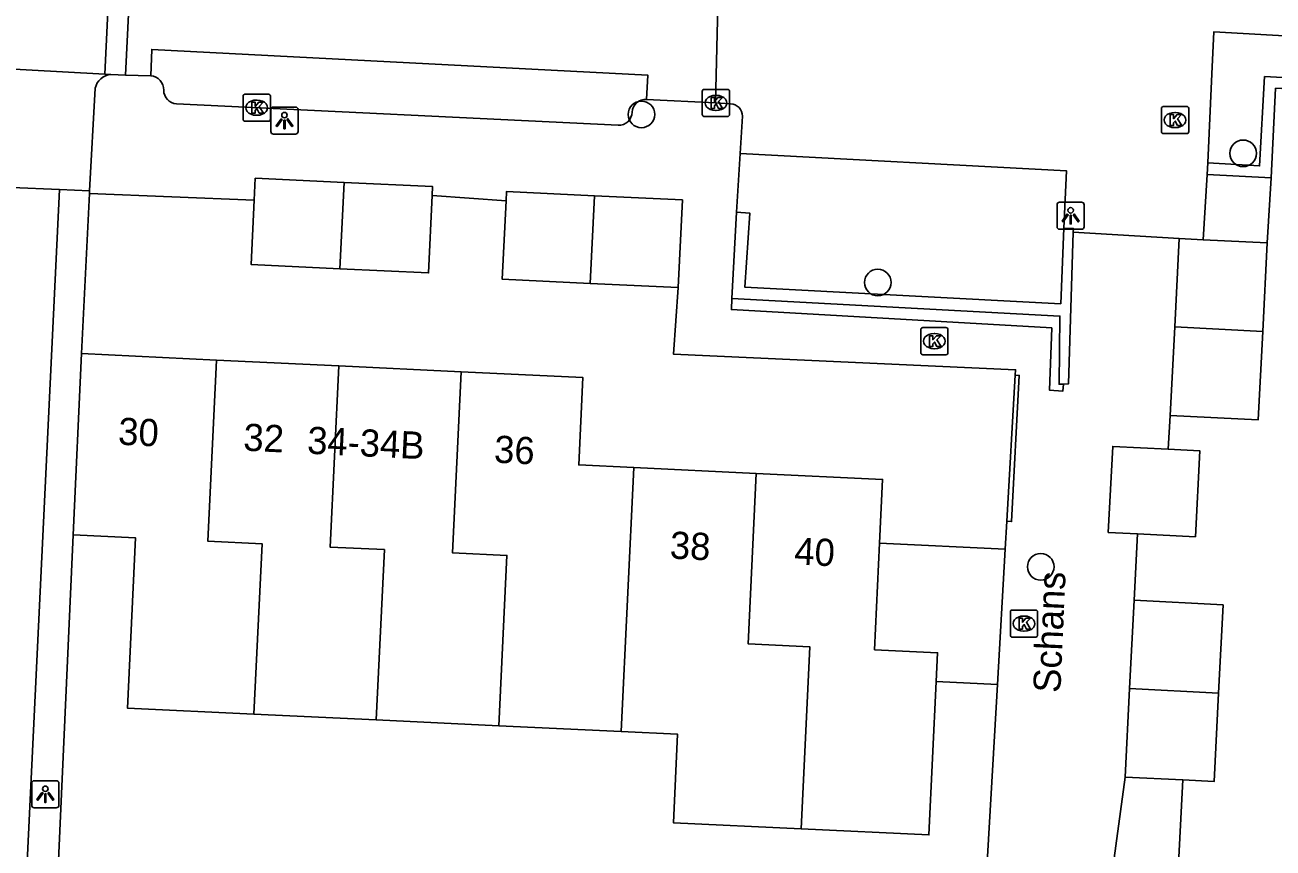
# Model space of a CAD drawing. Extents: x 162990 to 165007, y 383433 to 384336.
# Drawn here: x 164519.96 to 164565.87, y 383571.15 to 383601.43 of the extents above; entities that cross this region are included whole.
import ezdxf

# ---------------------------------------------------------------- set-up
doc = ezdxf.new("R2010")
doc.units = 0
for name, color, linetype in [('IMGEO_Boom', 7, 'Continuous'), ('IMGEO_Haag', 7, 'Continuous'), ('IMGEO_Kolk', 7, 'Continuous'), ('IMGEO_Lichtpunt', 7, 'Continuous'), ('IMGEO_Muur', 7, 'Continuous'), ('IMGEO_Openbare_ruimte_label', 7, 'Continuous'), ('IMGEO_Pand', 7, 'Continuous'), ('IMGEO_Pand_nummerreeks', 7, 'Continuous'), ('IMGEO_Parkeervlak_open', 7, 'Continuous'), ('IMGEO_Rijbaan_lokaal_open', 7, 'Continuous'), ('IMGEO_Voetpad_open', 7, 'Continuous')]:
    doc.layers.add(name, color=color, linetype=linetype)

msp = doc.modelspace()

# ---------------------------------------------------------------- linework, layer by layer
at = {"layer": 'IMGEO_Boom'}
for centre in [(164542.637, 383598.142), (164564.769, 383596.71), (164551.33, 383591.959), (164557.324, 383581.501)]:
    msp.add_circle(centre, 0.489, dxfattribs=at)
at = {"layer": 'IMGEO_Haag'}
msp.add_lwpolyline([(164556.385, 383588.543), (164556.077, 383583.176)], dxfattribs=at)
at = {"layer": 'IMGEO_Kolk'}
for p, q in [((164544.951, 383599.063), (164545.803, 383599.063)), ((164527.988, 383597.963), (164527.988, 383598.815)), ((164528.063, 383598.889), (164528.915, 383598.889)), ((164528.476, 383598.669), (164528.501, 383598.669)), ((164528.989, 383598.815), (164528.989, 383597.963)), ((164544.876, 383598.137), (164544.876, 383598.989)), ((164545.364, 383598.843), (164545.389, 383598.843)), ((164545.877, 383598.989), (164545.877, 383598.137)), ((164528.499, 383598.109), (164528.474, 383598.109)), ((164545.387, 383598.283), (164545.362, 383598.283)), ((164561.765, 383597.509), (164561.765, 383598.361)), ((164561.84, 383598.435), (164562.692, 383598.435)), ((164562.253, 383598.215), (164562.278, 383598.215)), ((164562.766, 383598.361), (164562.766, 383597.509)), ((164528.915, 383597.889), (164528.063, 383597.889)), ((164545.803, 383598.063), (164544.951, 383598.063)), ((164562.276, 383597.655), (164562.251, 383597.655)), ((164562.692, 383597.435), (164561.84, 383597.435)), ((164552.986, 383590.302), (164553.838, 383590.302)), ((164552.911, 383589.376), (164552.911, 383590.228)), ((164553.399, 383590.082), (164553.424, 383590.082)), ((164553.912, 383590.228), (164553.912, 383589.376)), ((164553.422, 383589.522), (164553.397, 383589.522)), ((164553.838, 383589.302), (164552.986, 383589.302)), ((164556.207, 383578.983), (164556.207, 383579.835)), ((164556.282, 383579.909), (164557.134, 383579.909)), ((164557.208, 383579.835), (164557.208, 383578.983)), ((164556.695, 383579.689), (164556.72, 383579.689)), ((164557.134, 383578.909), (164556.282, 383578.909)), ((164556.718, 383579.129), (164556.693, 383579.129))]:
    msp.add_line(p, q, dxfattribs=at)
for points in [[(164544.951, 383599.063), (164545.803, 383599.063)], [(164527.988, 383597.963), (164527.988, 383598.815)], [(164528.063, 383598.889), (164528.915, 383598.889)], [(164528.309, 383598.589), (164528.432, 383598.589), (164528.432, 383598.438), (164528.562, 383598.589), (164528.726, 383598.589), (164528.58, 383598.438), (164528.733, 383598.189), (164528.581, 383598.189), (164528.496, 383598.353), (164528.432, 383598.286), (164528.432, 383598.189), (164528.309, 383598.189), (164528.309, 383598.589)], [(164528.989, 383598.815), (164528.989, 383597.963)], [(164544.876, 383598.137), (164544.876, 383598.989)], [(164545.197, 383598.763), (164545.32, 383598.763), (164545.32, 383598.612), (164545.45, 383598.763), (164545.614, 383598.763), (164545.468, 383598.612), (164545.621, 383598.363), (164545.469, 383598.363), (164545.384, 383598.527), (164545.32, 383598.46), (164545.32, 383598.363), (164545.197, 383598.363), (164545.197, 383598.763)], [(164545.877, 383598.989), (164545.877, 383598.137)], [(164561.765, 383597.509), (164561.765, 383598.361)], [(164561.84, 383598.435), (164562.692, 383598.435)], [(164562.086, 383598.135), (164562.209, 383598.135), (164562.209, 383597.984), (164562.339, 383598.135), (164562.503, 383598.135), (164562.357, 383597.984), (164562.51, 383597.735), (164562.358, 383597.735), (164562.273, 383597.899), (164562.209, 383597.832), (164562.209, 383597.735), (164562.086, 383597.735), (164562.086, 383598.135)], [(164562.766, 383598.361), (164562.766, 383597.509)], [(164528.915, 383597.889), (164528.063, 383597.889)], [(164545.803, 383598.063), (164544.951, 383598.063)], [(164562.692, 383597.435), (164561.84, 383597.435)], [(164552.986, 383590.302), (164553.838, 383590.302)], [(164552.911, 383589.376), (164552.911, 383590.228)], [(164553.232, 383590.002), (164553.355, 383590.002), (164553.355, 383589.851), (164553.485, 383590.002), (164553.649, 383590.002), (164553.503, 383589.851), (164553.656, 383589.602), (164553.504, 383589.602), (164553.419, 383589.766), (164553.355, 383589.699), (164553.355, 383589.602), (164553.232, 383589.602), (164553.232, 383590.002)], [(164553.912, 383590.228), (164553.912, 383589.376)], [(164553.838, 383589.302), (164552.986, 383589.302)], [(164556.207, 383578.983), (164556.207, 383579.835)], [(164556.282, 383579.909), (164557.134, 383579.909)], [(164557.208, 383579.835), (164557.208, 383578.983)], [(164556.528, 383579.609), (164556.651, 383579.609), (164556.651, 383579.458), (164556.781, 383579.609), (164556.945, 383579.609), (164556.799, 383579.458), (164556.952, 383579.209), (164556.8, 383579.209), (164556.715, 383579.373), (164556.651, 383579.306), (164556.651, 383579.209), (164556.528, 383579.209), (164556.528, 383579.609)], [(164557.134, 383578.909), (164556.282, 383578.909)]]:
    msp.add_lwpolyline(points, dxfattribs=at)
for centre, start, end in [((164544.953, 383598.987), 91.552, 178.448), ((164544.953, 383598.987), 91.552, 178.448), ((164545.801, 383598.987), 1.552, 88.448), ((164545.801, 383598.987), 1.552, 88.448), ((164528.065, 383598.813), 91.552, 178.448), ((164528.065, 383598.813), 91.552, 178.448), ((164528.913, 383598.813), 1.552, 88.448), ((164528.913, 383598.813), 1.552, 88.448), ((164544.953, 383598.139), 181.552, 268.448), ((164544.953, 383598.139), 181.552, 268.448), ((164545.801, 383598.139), 271.552, 358.448), ((164545.801, 383598.139), 271.552, 358.448), ((164561.842, 383598.359), 91.552, 178.448), ((164561.842, 383598.359), 91.552, 178.448), ((164562.69, 383598.359), 1.552, 88.448), ((164562.69, 383598.359), 1.552, 88.448), ((164528.065, 383597.965), 181.552, 268.448), ((164528.065, 383597.965), 181.552, 268.448), ((164528.913, 383597.965), 271.552, 358.448), ((164528.913, 383597.965), 271.552, 358.448), ((164561.842, 383597.511), 181.552, 268.448), ((164561.842, 383597.511), 181.552, 268.448), ((164562.69, 383597.511), 271.552, 358.448), ((164562.69, 383597.511), 271.552, 358.448), ((164552.988, 383590.226), 91.552, 178.448), ((164552.988, 383590.226), 91.552, 178.448), ((164553.836, 383590.226), 1.552, 88.448), ((164553.836, 383590.226), 1.552, 88.448), ((164552.988, 383589.378), 181.552, 268.448), ((164552.988, 383589.378), 181.552, 268.448), ((164553.836, 383589.378), 271.552, 358.448), ((164553.836, 383589.378), 271.552, 358.448), ((164556.284, 383579.833), 91.552, 178.448), ((164556.284, 383579.833), 91.552, 178.448), ((164557.132, 383579.833), 1.552, 88.448), ((164557.132, 383579.833), 1.552, 88.448), ((164556.284, 383578.985), 181.552, 268.448), ((164556.284, 383578.985), 181.552, 268.448), ((164557.132, 383578.985), 271.552, 358.448), ((164557.132, 383578.985), 271.552, 358.448)]:
    msp.add_arc(centre, 0.0765, start, end, dxfattribs=at)
for centre, major_axis, ratio, start_param, end_param in [((164528.475, 383598.389), (-0.387, 0.002), 0.722429, 4.712389, 7.853982), ((164528.5, 383598.389), (-0.39, 0.002), 0.717154, 1.570796, 4.712389), ((164545.363, 383598.563), (-0.387, 0.002), 0.722429, 4.712389, 7.853982), ((164545.388, 383598.563), (-0.39, 0.002), 0.717154, 1.570796, 4.712389), ((164562.252, 383597.935), (-0.387, 0.002), 0.722429, 4.712389, 7.853982), ((164562.277, 383597.935), (-0.39, 0.002), 0.717154, 1.570796, 4.712389), ((164553.398, 383589.802), (-0.387, 0.002), 0.722429, 4.712389, 7.853982), ((164553.423, 383589.802), (-0.39, 0.002), 0.717154, 1.570796, 4.712389), ((164556.694, 383579.409), (-0.387, 0.002), 0.722429, 4.712389, 7.853982), ((164556.719, 383579.409), (-0.39, 0.002), 0.717154, 1.570796, 4.712389)]:
    msp.add_ellipse(centre, major_axis=major_axis, ratio=ratio, start_param=start_param, end_param=end_param, dxfattribs=at)
at = {"layer": 'IMGEO_Lichtpunt'}
for p, q in [((164529.01, 383598.318), (164529.01, 383597.511)), ((164529.01, 383598.318), (164529.01, 383597.511)), ((164529.912, 383598.413), (164529.104, 383598.413)), ((164529.912, 383598.413), (164529.104, 383598.413)), ((164530.006, 383597.511), (164530.006, 383598.318)), ((164530.006, 383597.511), (164530.006, 383598.318)), ((164529.104, 383597.417), (164529.912, 383597.417)), ((164529.104, 383597.417), (164529.912, 383597.417)), ((164558.828, 383594.911), (164558.02, 383594.911)), ((164558.828, 383594.911), (164558.02, 383594.911)), ((164557.926, 383594.816), (164557.926, 383594.009)), ((164557.926, 383594.816), (164557.926, 383594.009)), ((164558.922, 383594.009), (164558.922, 383594.816)), ((164558.922, 383594.009), (164558.922, 383594.816)), ((164558.02, 383593.915), (164558.828, 383593.915)), ((164558.02, 383593.915), (164558.828, 383593.915)), ((164520.214, 383573.536), (164520.214, 383572.729)), ((164520.214, 383573.536), (164520.214, 383572.729)), ((164521.116, 383573.631), (164520.308, 383573.631)), ((164521.116, 383573.631), (164520.308, 383573.631)), ((164521.21, 383572.729), (164521.21, 383573.536)), ((164521.21, 383572.729), (164521.21, 383573.536)), ((164520.308, 383572.635), (164521.116, 383572.635)), ((164520.308, 383572.635), (164521.116, 383572.635))]:
    msp.add_line(p, q, dxfattribs=at)
for points in [[(164529.384, 383597.982), (164529.423, 383597.954), (164529.235, 383597.692), (164529.197, 383597.719), (164529.384, 383597.982)], [(164529.486, 383597.934), (164529.533, 383597.934), (164529.533, 383597.612), (164529.486, 383597.612), (164529.486, 383597.934)], [(164529.596, 383597.954), (164529.634, 383597.981), (164529.821, 383597.719), (164529.782, 383597.691), (164529.596, 383597.954)], [(164558.3, 383594.48), (164558.339, 383594.452), (164558.151, 383594.19), (164558.113, 383594.217), (164558.3, 383594.48)], [(164558.402, 383594.432), (164558.449, 383594.432), (164558.449, 383594.11), (164558.402, 383594.11), (164558.402, 383594.432)], [(164558.512, 383594.452), (164558.55, 383594.479), (164558.737, 383594.217), (164558.698, 383594.189), (164558.512, 383594.452)], [(164520.588, 383573.2), (164520.627, 383573.172), (164520.439, 383572.91), (164520.401, 383572.937), (164520.588, 383573.2)], [(164520.69, 383573.152), (164520.737, 383573.152), (164520.737, 383572.83), (164520.69, 383572.83), (164520.69, 383573.152)], [(164520.8, 383573.172), (164520.838, 383573.199), (164521.025, 383572.937), (164520.986, 383572.909), (164520.8, 383573.172)]]:
    msp.add_lwpolyline(points, dxfattribs=at)
for centre in [(164529.509, 383598.116), (164558.425, 383594.614), (164520.713, 383573.334)]:
    msp.add_circle(centre, 0.0994, dxfattribs=at)
for centre, start, end in [((164529.104, 383598.318), 90, 180), ((164529.104, 383598.318), 90, 180), ((164529.912, 383598.318), 0, 90), ((164529.912, 383598.318), 0, 90), ((164529.104, 383597.511), 180, 270), ((164529.104, 383597.511), 180, 270), ((164529.912, 383597.511), 270, 0), ((164529.912, 383597.511), 270, 360), ((164558.02, 383594.816), 90, 180), ((164558.02, 383594.816), 90, 180), ((164558.828, 383594.816), 0, 90), ((164558.828, 383594.816), 0, 90), ((164558.02, 383594.009), 180, 270), ((164558.02, 383594.009), 180, 270), ((164558.828, 383594.009), 270, 0), ((164558.828, 383594.009), 270, 360), ((164520.308, 383573.536), 90, 180), ((164520.308, 383573.536), 90, 180), ((164521.116, 383573.536), 0, 90), ((164521.116, 383573.536), 0, 90), ((164520.308, 383572.729), 180, 270), ((164520.308, 383572.729), 180, 270), ((164521.116, 383572.729), 270, 0), ((164521.116, 383572.729), 270, 360)]:
    msp.add_arc(centre, 0.0946, start, end, dxfattribs=at)
at = {"layer": 'IMGEO_Muur'}
for points in [[(164563.466, 383596.357), (164565.372, 383596.247), (164565.556, 383599.531), (164570.369, 383599.262)], [(164570.349, 383598.879), (164565.965, 383599.104), (164565.796, 383595.808)], [(164563.44, 383595.929), (164563.466, 383596.357)], [(164565.796, 383595.808), (164563.44, 383595.929)], [(164545.958, 383591.369), (164546.139, 383594.544)], [(164558.178, 383593.954), (164558.06, 383591.174), (164546.443, 383591.785), (164546.621, 383594.514), (164546.139, 383594.544)], [(164558.521, 383593.815), (164558.346, 383588.235), (164558.156, 383588.224)], [(164558.178, 383593.954), (164558.525, 383593.945), (164558.521, 383593.815)], [(164558.156, 383588.224), (164557.996, 383588.215), (164558.03, 383590.725), (164545.958, 383591.369)], [(164521.732, 383582.678), (164521.067, 383567.706)]]:
    msp.add_lwpolyline(points, dxfattribs=at)
at = {"layer": 'IMGEO_Pand'}
for points in [[(164528.397, 383594.983), (164528.436, 383595.795), (164531.698, 383595.639)], [(164531.698, 383595.639), (164531.545, 383592.465)], [(164531.698, 383595.639), (164534.958, 383595.484), (164534.942, 383595.154)], [(164531.545, 383592.465), (164528.284, 383592.62), (164528.397, 383594.983)], [(164534.942, 383595.154), (164534.806, 383592.309), (164531.545, 383592.465)], [(164540.758, 383591.924), (164537.52, 383592.078), (164537.658, 383594.958)], [(164537.658, 383594.958), (164537.674, 383595.303), (164540.912, 383595.149)], [(164540.912, 383595.149), (164540.758, 383591.924)], [(164540.912, 383595.149), (164544.148, 383594.995), (164543.994, 383591.77)], [(164562.251, 383590.325), (164562.417, 383593.578)], [(164562.417, 383593.578), (164563.296, 383593.533)], [(164565.653, 383593.412), (164563.296, 383593.533)], [(164565.653, 383593.412), (164565.487, 383590.158)], [(164543.994, 383591.77), (164540.758, 383591.924)], [(164562.085, 383587.069), (164562.251, 383590.325)], [(164565.487, 383590.158), (164562.251, 383590.325)], [(164565.487, 383590.158), (164565.32, 383586.903), (164562.085, 383587.069)], [(164521.732, 383582.678), (164522.049, 383589.34)], [(164522.049, 383589.34), (164527.005, 383589.104)], [(164527.005, 383589.104), (164526.685, 383582.443), (164528.683, 383582.347), (164528.383, 383576.08)], [(164527.005, 383589.104), (164531.508, 383588.889)], [(164532.886, 383575.865), (164533.186, 383582.131), (164531.188, 383582.227), (164531.508, 383588.889)], [(164531.508, 383588.889), (164536.011, 383588.674)], [(164536.011, 383588.674), (164535.691, 383582.012), (164537.689, 383581.916), (164537.389, 383575.651)], [(164536.011, 383588.674), (164540.488, 383588.461), (164540.335, 383585.247), (164542.356, 383585.151)], [(164560.885, 383582.711), (164559.81, 383582.766), (164559.972, 383585.926), (164562.014, 383585.822)], [(164562.014, 383585.822), (164563.178, 383585.762), (164563.016, 383582.602), (164560.885, 383582.711)], [(164541.891, 383575.436), (164542.356, 383585.151)], [(164542.356, 383585.151), (164546.859, 383584.936)], [(164546.859, 383584.936), (164546.559, 383578.666), (164548.831, 383578.558), (164548.51, 383571.861)], [(164551.397, 383582.369), (164551.509, 383584.714), (164546.859, 383584.936)], [(164528.383, 383576.08), (164523.729, 383576.302), (164524.028, 383582.568), (164521.732, 383582.678)], [(164551.397, 383582.369), (164551.21, 383578.445), (164553.528, 383578.335), (164553.477, 383577.274)], [(164556.018, 383582.149), (164551.397, 383582.369)], [(164555.732, 383577.167), (164556.018, 383582.149)], [(164560.592, 383577.018), (164560.758, 383580.268)], [(164560.758, 383580.268), (164564.033, 383580.1), (164563.867, 383576.85)], [(164548.51, 383571.861), (164553.209, 383571.637), (164553.477, 383577.274)], [(164553.477, 383577.274), (164555.732, 383577.167)], [(164560.425, 383573.766), (164560.592, 383577.018)], [(164560.592, 383577.018), (164563.867, 383576.85)], [(164563.867, 383576.85), (164563.7, 383573.599), (164562.554, 383573.657)], [(164532.886, 383575.865), (164528.383, 383576.08)], [(164537.389, 383575.651), (164532.886, 383575.865)], [(164541.891, 383575.436), (164537.389, 383575.651)], [(164548.51, 383571.861), (164543.812, 383572.085), (164543.967, 383575.337), (164541.891, 383575.436)], [(164562.554, 383573.657), (164560.425, 383573.766)]]:
    msp.add_lwpolyline(points, dxfattribs=at)
at = {"layer": 'IMGEO_Parkeervlak_open'}
msp.add_lwpolyline([(164565.796, 383595.808), (164565.653, 383593.412)], dxfattribs=at)
at = {"layer": 'IMGEO_Rijbaan_lokaal_open'}
for points in [[(164523.905, 383604.582), (164523.657, 383599.59)], [(164545.495, 383604.162), (164545.356, 383598.562)], [(164522.898, 383599.619), (164523.089, 383603.477)], [(164568.002, 383600.929), (164563.688, 383601.174), (164563.617, 383599.634), (164563.466, 383596.357)], [(164524.589, 383599.563), (164524.628, 383600.535), (164542.87, 383599.588), (164542.826, 383598.688)], [(164522.898, 383599.619), (164515.991, 383600.008)], [(164523.123, 383599.606), (164522.898, 383599.619)], [(164523.657, 383599.59), (164523.123, 383599.606)], [(164524.589, 383599.563), (164523.657, 383599.59)], [(164545.356, 383598.562), (164542.826, 383598.688)], [(164545.917, 383598.534), (164545.54, 383598.553), (164545.356, 383598.562)], [(164546.27, 383596.701), (164546.35, 383598.074)], [(164546.27, 383596.701), (164558.268, 383596.07), (164558.178, 383593.954)], [(164563.296, 383593.533), (164563.44, 383595.929)], [(164521.228, 383595.378), (164519.5, 383559.415), (164514.596, 383559.651), (164515.073, 383569.579)], [(164517.713, 383595.532), (164521.228, 383595.378)], [(164562.417, 383593.578), (164558.521, 383593.815)]]:
    msp.add_lwpolyline(points, dxfattribs=at)
msp.add_arc((164545.897, 383598.082), 0.453, 359.0251, 87.5113, dxfattribs=at)
at = {"layer": 'IMGEO_Voetpad_open'}
for points in [[(164522.549, 383599.106), (164522.342, 383595.329)], [(164541.782, 383597.744), (164525.539, 383598.532)], [(164546.139, 383594.544), (164546.27, 383596.701)], [(164522.342, 383595.329), (164521.228, 383595.378)], [(164522.049, 383589.34), (164522.337, 383595.229)], [(164522.342, 383595.329), (164522.337, 383595.229)], [(164522.337, 383595.229), (164528.397, 383594.983)], [(164534.942, 383595.154), (164537.658, 383594.958)], [(164543.994, 383591.77), (164543.816, 383589.324), (164556.397, 383588.748), (164556.385, 383588.543)], [(164545.958, 383591.369), (164545.947, 383590.963), (164557.729, 383590.289), (164557.644, 383588.002), (164558.137, 383587.966), (164558.156, 383588.224)], [(164556.077, 383583.176), (164556.255, 383583.163), (164556.537, 383588.541), (164556.385, 383588.543)], [(164562.014, 383585.822), (164562.085, 383587.069)], [(164556.077, 383583.176), (164556.018, 383582.149)], [(164521.732, 383582.678), (164521.067, 383567.706)], [(164560.758, 383580.268), (164560.885, 383582.711)], [(164555.732, 383577.167), (164555.261, 383568.946)], [(164559.746, 383568.703), (164560.425, 383573.766)], [(164562.554, 383573.657), (164562.007, 383563.198), (164563.725, 383563.04)]]:
    msp.add_lwpolyline(points, dxfattribs=at)
for centre, radius, start, end in [((164523.16, 383598.984), 0.624, 93.4429, 168.674), ((164524.549, 383599.046), 0.518, 358.5553, 85.5385), ((164525.57, 383599.034), 0.503, 180.1185, 266.4672), ((164542.779, 383598.202), 0.488, 84.4345, 177.0672), ((164541.813, 383598.221), 0.478, 266.2383, 0.759)]:
    msp.add_arc(centre, radius, start, end, dxfattribs=at)

# ---------------------------------------------------------------- texts
at = {"layer": 'IMGEO_Openbare_ruimte_label'}
msp.add_text('Schans', height=1, rotation=87.4781, dxfattribs=at).set_placement((164558.044, 383576.848))
at = {"layer": 'IMGEO_Pand_nummerreeks'}
for s, rotation, p in [('30', 357.2707, (164523.376, 383585.993)), ('32', 357.2707, (164527.98, 383585.774)), ('34-34B', 357.2664, (164530.328, 383585.662)), ('36', 357.2707, (164537.202, 383585.334)), ('38', 357.2691, (164543.666, 383581.805)), ('40', 357.267, (164548.243, 383581.586))]:
    msp.add_text(s, height=1, rotation=rotation, dxfattribs=at).set_placement(p)

doc.saveas('drawing.dxf')
